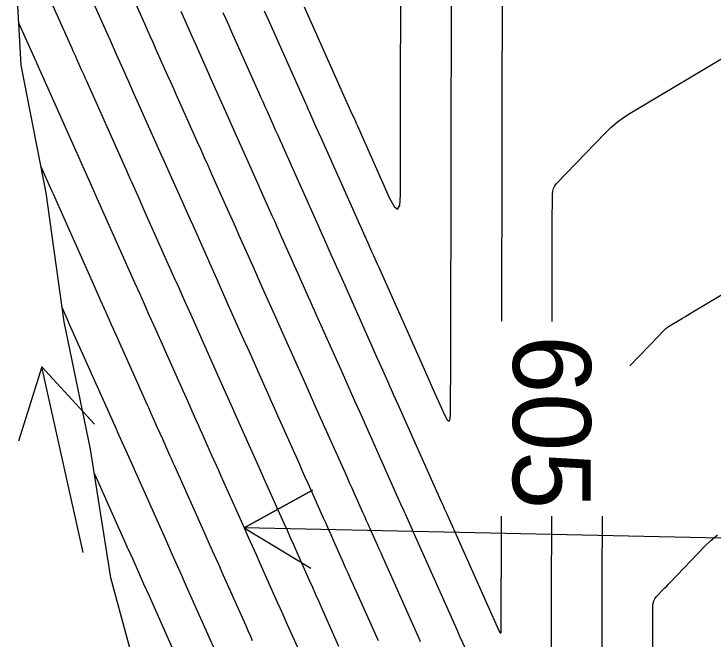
# Model space of a CAD drawing. Extents: x 954385 to 988206, y 1868364 to 1924553.
# Drawn here: x 958001.8 to 958055.6, y 1918662.3 to 1918710.4 of the extents above; entities that cross this region are included whole.
import ezdxf

# ---------------------------------------------------------------- set-up
doc = ezdxf.new("R2010")
doc.units = 0
for name, color, linetype in [('24', 7, 'Continuous'), ('26', 7, 'Continuous'), ('5', 7, 'Continuous'), ('6', 7, 'Continuous'), ('7', 7, 'Continuous')]:
    doc.layers.add(name, color=color, linetype=linetype)

msp = doc.modelspace()

# ---------------------------------------------------------------- linework, layer by layer
at = {"layer": '24'}
msp.add_lwpolyline([(958049.573, 1918532.557), (958045.001, 1918541.78), (958040.731, 1918551.071), (958036.858, 1918560.45), (958033.237, 1918569.886), (958029.666, 1918579.334), (958026.587, 1918588.891), (958024.254, 1918598.617), (958022.107, 1918608.383), (958020.314, 1918618.23), (958018.751, 1918628.128), (958016.763, 1918637.93), (958014.212, 1918647.607), (958011.88, 1918657.332), (958009.258, 1918666.992), (958007.706, 1918676.893), (958005.664, 1918686.683), (958004.274, 1918696.62), (958002.36, 1918706.439), (958001.804, 1918716.563)], dxfattribs=at)
at = {"layer": '26'}
for points in [[(958007.131, 1918668.928), (958003.951, 1918683.225), (958008.008, 1918678.804), (958003.951, 1918683.225), (958002.151, 1918677.502)], [(958107.131, 1918668.928), (958019.526, 1918670.834), (958024.786, 1918673.72), (958019.526, 1918670.834), (958024.656, 1918667.722)]]:
    msp.add_lwpolyline(points, dxfattribs=at)
at = {"layer": '6'}
for points in [[(958014.64, 1918710.621), (958014.93, 1918709.973), (958015.219, 1918709.325), (958015.509, 1918708.677), (958015.798, 1918708.029), (958017.073, 1918705.173), (958017.303, 1918704.656), (958017.534, 1918704.14), (958017.764, 1918703.623), (958017.995, 1918703.107), (958018.917, 1918701.042), (958019.147, 1918700.525), (958019.378, 1918700.009), (958019.609, 1918699.493), (958019.839, 1918698.976), (958021.671, 1918694.873), (958021.858, 1918694.455), (958022.044, 1918694.037), (958022.231, 1918693.619), (958022.417, 1918693.201), (958023.228, 1918691.386), (958023.382, 1918691.04), (958023.537, 1918690.694), (958023.691, 1918690.348), (958023.846, 1918690.002), (958024.464, 1918688.618), (958024.618, 1918688.271), (958024.773, 1918687.925), (958024.927, 1918687.579), (958025.081, 1918687.233), (958026.964, 1918683.015), (958027.33, 1918682.197), (958027.695, 1918681.378), (958028.06, 1918680.56), (958028.426, 1918679.741), (958030.835, 1918674.344), (958030.937, 1918674.116), (958031.039, 1918673.888), (958031.14, 1918673.66), (958031.242, 1918673.432), (958031.679, 1918672.454), (958031.766, 1918672.259), (958031.854, 1918672.063), (958031.941, 1918671.867), (958032.028, 1918671.672), (958032.377, 1918670.89), (958032.464, 1918670.694), (958032.552, 1918670.498), (958032.639, 1918670.303), (958032.726, 1918670.107), (958035.901, 1918662.994), (958035.957, 1918662.87), (958036.012, 1918662.747), (958036.067, 1918662.624), (958036.122, 1918662.5), (958036.563, 1918661.512)], [(958043.244, 1918686.729), (958043.26, 1918694.15), (958043.265, 1918696.527), (958043.286, 1918696.754), (958043.347, 1918696.964), (958043.449, 1918697.157), (958043.591, 1918697.335), (958047.331, 1918701.226), (958047.774, 1918701.658), (958048.243, 1918702.057), (958048.738, 1918702.424), (958049.258, 1918702.758), (958057.444, 1918707.645)], [(958020.184, 1918662.132), (958020.014, 1918662.513), (958019.844, 1918662.894), (958019.674, 1918663.276), (958017.918, 1918667.212), (958017.569, 1918667.995), (958017.219, 1918668.779), (958016.869, 1918669.562), (958016.52, 1918670.345), (958014.179, 1918675.587), (958014.067, 1918675.837), (958013.955, 1918676.088), (958013.843, 1918676.339), (958013.731, 1918676.59), (958013.255, 1918677.656), (958013.06, 1918678.094), (958012.864, 1918678.533), (958012.375, 1918679.629), (958012.179, 1918680.067), (958012.081, 1918680.286), (958009.745, 1918685.519), (958009.323, 1918686.464), (958008.901, 1918687.41), (958008.479, 1918688.355), (958008.057, 1918689.3), (958004.835, 1918696.517), (958004.722, 1918696.771), (958003.875, 1918698.668)], [(958043.175, 1918655.381), (958043.193, 1918662.483), (958043.195, 1918663.421), (958043.197, 1918664.36), (958043.199, 1918665.298), (958043.201, 1918666.236), (958043.212, 1918671.179), (958043.213, 1918671.729)]]:
    msp.add_lwpolyline(points, dxfattribs=at)
at = {"layer": '7'}
for points in [[(958002.39, 1918716.411), (958006.254, 1918707.765), (958006.346, 1918707.56), (958006.438, 1918707.354), (958006.529, 1918707.149), (958006.621, 1918706.943), (958006.988, 1918706.121), (958007.08, 1918705.915), (958007.172, 1918705.71), (958007.263, 1918705.504), (958007.355, 1918705.299), (958010.318, 1918698.664), (958010.457, 1918698.351), (958010.597, 1918698.039), (958010.736, 1918697.726), (958010.876, 1918697.414), (958011.434, 1918696.164), (958011.713, 1918695.539), (958011.992, 1918694.914), (958014.125, 1918690.134), (958014.44, 1918689.429), (958014.755, 1918688.723), (958015.07, 1918688.018), (958015.385, 1918687.312), (958016.865, 1918683.997), (958017.07, 1918683.538), (958017.275, 1918683.079), (958017.48, 1918682.62), (958017.685, 1918682.161), (958018.504, 1918680.326), (958018.709, 1918679.867), (958018.914, 1918679.408), (958019.119, 1918678.949), (958019.323, 1918678.49), (958020.32, 1918676.258), (958020.554, 1918675.733), (958020.789, 1918675.208), (958021.023, 1918674.683), (958021.257, 1918674.158), (958022.583, 1918671.189), (958022.828, 1918670.64), (958023.073, 1918670.092), (958023.317, 1918669.544), (958023.562, 1918668.996), (958024.54, 1918666.803), (958024.785, 1918666.255), (958025.029, 1918665.707), (958025.274, 1918665.159), (958025.518, 1918664.611), (958026.805, 1918661.728)], [(958006.033, 1918715.467), (958009.049, 1918708.717), (958009.207, 1918708.364), (958009.365, 1918708.011), (958009.522, 1918707.658), (958009.68, 1918707.305), (958010.31, 1918705.893), (958010.468, 1918705.54), (958010.626, 1918705.187), (958010.783, 1918704.834), (958010.941, 1918704.48), (958013.116, 1918699.61), (958013.32, 1918699.153), (958013.524, 1918698.696), (958013.728, 1918698.238), (958013.932, 1918697.781), (958014.748, 1918695.952), (958014.952, 1918695.495), (958015.157, 1918695.038), (958015.361, 1918694.581), (958015.565, 1918694.124), (958017.16, 1918690.552), (958017.421, 1918689.966), (958017.683, 1918689.38), (958017.944, 1918688.794), (958018.205, 1918688.209), (958019.258, 1918685.852), (958019.516, 1918685.273), (958019.774, 1918684.694), (958020.033, 1918684.116), (958020.291, 1918683.537), (958021.324, 1918681.222), (958021.583, 1918680.643), (958021.841, 1918680.065), (958022.099, 1918679.486), (958022.358, 1918678.907), (958023.757, 1918675.773), (958023.981, 1918675.271), (958024.205, 1918674.768), (958024.43, 1918674.266), (958024.654, 1918673.763), (958025.615, 1918671.61), (958025.808, 1918671.18), (958026, 1918670.749), (958026.192, 1918670.319), (958026.384, 1918669.888), (958027.152, 1918668.166), (958027.345, 1918667.735), (958027.537, 1918667.304), (958027.729, 1918666.874), (958027.921, 1918666.443), (958029.837, 1918662.15)], [(958009.676, 1918714.523), (958011.845, 1918709.669), (958012.068, 1918709.168), (958012.292, 1918708.668), (958012.515, 1918708.167), (958012.739, 1918707.667), (958013.633, 1918705.664), (958013.856, 1918705.164), (958014.08, 1918704.663), (958014.303, 1918704.163), (958014.527, 1918703.662), (958015.913, 1918700.556), (958016.182, 1918699.954), (958016.451, 1918699.352), (958016.72, 1918698.75), (958016.988, 1918698.149), (958018.098, 1918695.663), (958018.349, 1918695.1), (958018.6, 1918694.537), (958018.852, 1918693.975), (958019.103, 1918693.412), (958020.194, 1918690.969), (958020.402, 1918690.503), (958020.61, 1918690.037), (958020.818, 1918689.571), (958021.026, 1918689.105), (958021.857, 1918687.242), (958022.065, 1918686.776), (958022.273, 1918686.31), (958022.481, 1918685.844), (958022.689, 1918685.378), (958024.144, 1918682.119), (958024.456, 1918681.42), (958024.768, 1918680.721), (958025.08, 1918680.023), (958025.392, 1918679.324), (958027.296, 1918675.059), (958027.459, 1918674.693), (958027.622, 1918674.328), (958027.785, 1918673.963), (958027.948, 1918673.598), (958028.647, 1918672.032), (958028.787, 1918671.719), (958028.927, 1918671.406), (958029.066, 1918671.093), (958029.206, 1918670.78), (958029.765, 1918669.528), (958029.904, 1918669.214), (958030.044, 1918668.901), (958030.184, 1918668.588), (958030.324, 1918668.275), (958032.869, 1918662.572), (958032.977, 1918662.331), (958033.084, 1918662.09)], [(958021.074, 1918710.639), (958021.225, 1918710.3), (958021.376, 1918709.962), (958024.244, 1918703.536), (958024.343, 1918703.314), (958024.442, 1918703.093), (958024.541, 1918702.872), (958024.639, 1918702.65), (958025.035, 1918701.765), (958025.232, 1918701.323), (958025.43, 1918700.88), (958028.817, 1918693.293), (958029.047, 1918692.779), (958029.343, 1918692.114), (958029.486, 1918691.795), (958029.771, 1918691.156), (958029.866, 1918690.944), (958033.08, 1918683.742), (958033.315, 1918683.217), (958033.549, 1918682.692), (958033.784, 1918682.167), (958034.018, 1918681.642), (958034.956, 1918679.541), (958035.161, 1918679.153), (958035.308, 1918679.041), (958035.397, 1918679.203), (958035.427, 1918679.641), (958035.437, 1918684.053), (958035.441, 1918685.93), (958035.442, 1918686.399), (958035.443, 1918686.868), (958035.444, 1918687.337), (958035.445, 1918687.806), (958035.46, 1918694.994), (958035.473, 1918701.059), (958035.475, 1918702.34), (958035.478, 1918703.622), (958035.481, 1918704.904), (958035.483, 1918706.185), (958035.496, 1918712.107)], [(958039.396, 1918712.046), (958039.378, 1918703.055), (958039.366, 1918697.605), (958039.348, 1918688.682), (958039.347, 1918688.213), (958039.346, 1918687.744), (958039.345, 1918687.275), (958039.344, 1918686.806), (958039.344, 1918686.737)], [(958024.16, 1918710.939), (958027.83, 1918702.717), (958027.962, 1918702.422), (958028.159, 1918701.98), (958028.225, 1918701.832), (958030.707, 1918696.272), (958031.079, 1918695.57), (958031.346, 1918695.366), (958031.506, 1918695.66), (958031.561, 1918696.453), (958031.57, 1918700.652), (958031.573, 1918701.699), (958031.575, 1918702.746), (958031.577, 1918703.793), (958031.579, 1918704.84), (958031.593, 1918711.378)], [(958039.312, 1918671.737), (958039.312, 1918671.677), (958039.311, 1918671.333), (958039.31, 1918670.99), (958039.31, 1918670.646), (958039.309, 1918670.303), (958039.294, 1918663.701), (958039.294, 1918663.592), (958039.294, 1918663.484), (958039.294, 1918663.375), (958039.293, 1918663.266), (958039.292, 1918662.817), (958039.287, 1918662.739), (958039.271, 1918662.711), (958039.245, 1918662.731), (958039.209, 1918662.799), (958038.936, 1918663.41), (958038.933, 1918663.416), (958035.129, 1918671.939), (958035.059, 1918672.096), (958034.989, 1918672.252), (958034.85, 1918672.564), (958034.781, 1918672.72), (958034.711, 1918672.876), (958034.496, 1918673.357), (958034.374, 1918673.63), (958031.46, 1918680.158), (958031.041, 1918681.097), (958030.622, 1918682.035), (958030.203, 1918682.973), (958029.784, 1918683.911), (958027.474, 1918689.088), (958027.272, 1918689.541), (958027.07, 1918689.993), (958026.666, 1918690.898), (958026.464, 1918691.351), (958026.262, 1918691.803), (958025.732, 1918692.99), (958025.488, 1918693.536), (958025.244, 1918694.083), (958022.634, 1918699.928), (958022.47, 1918700.297), (958022.305, 1918700.666), (958022.14, 1918701.035), (958021.976, 1918701.404), (958021.317, 1918702.879), (958021.152, 1918703.248), (958020.988, 1918703.616), (958020.823, 1918703.985), (958020.659, 1918704.354), (958018.591, 1918708.985), (958018.369, 1918709.483), (958018.146, 1918709.982), (958017.924, 1918710.48)], [(958002.183, 1918709.668), (958003.459, 1918706.813), (958003.51, 1918706.697), (958003.562, 1918706.581), (958003.717, 1918706.233), (958003.769, 1918706.117), (958007.52, 1918697.718), (958007.669, 1918697.382), (958007.819, 1918697.046), (958008.194, 1918696.207), (958008.419, 1918695.704), (958011.091, 1918689.717), (958011.46, 1918688.892), (958011.828, 1918688.066), (958012.197, 1918687.241), (958012.565, 1918686.416), (958014.473, 1918682.141), (958014.625, 1918681.802), (958014.776, 1918681.463), (958014.927, 1918681.124), (958015.079, 1918680.785), (958015.684, 1918679.429), (958015.835, 1918679.09), (958015.987, 1918678.751), (958016.138, 1918678.412), (958016.289, 1918678.073), (958017.026, 1918676.424), (958017.199, 1918676.036), (958017.372, 1918675.648), (958017.545, 1918675.26), (958017.718, 1918674.873), (958019.552, 1918670.767), (958019.849, 1918670.101), (958020.146, 1918669.435), (958020.443, 1918668.77), (958020.74, 1918668.104), (958022.077, 1918665.108), (958022.299, 1918664.609), (958022.522, 1918664.11), (958022.744, 1918663.611), (958022.967, 1918663.112), (958023.858, 1918661.117)], [(958049.237, 1918683.307), (958051.463, 1918685.623), (958051.702, 1918685.871), (958051.94, 1918686.119), (958052.001, 1918686.179), (958052.066, 1918686.234), (958052.135, 1918686.285), (958052.207, 1918686.332), (958053.271, 1918686.967), (958053.473, 1918687.088), (958053.675, 1918687.209), (958053.877, 1918687.329), (958054.079, 1918687.45), (958060.723, 1918691.422)], [(958017.271, 1918661.443), (958015.096, 1918666.32), (958014.694, 1918667.221), (958014.292, 1918668.122), (958013.89, 1918669.022), (958013.488, 1918669.923), (958010.64, 1918676.301), (958010.538, 1918676.528), (958010.437, 1918676.756), (958010.133, 1918677.437), (958009.778, 1918678.232), (958009.689, 1918678.431), (958006.091, 1918686.492), (958005.916, 1918686.883), (958005.508, 1918687.796)], [(958008.004, 1918674.993), (958010.525, 1918669.347), (958010.945, 1918668.406), (958011.365, 1918667.465), (958011.785, 1918666.524), (958012.205, 1918665.583), (958014.869, 1918659.611)], [(958047.078, 1918656.257), (958047.096, 1918663.642), (958047.098, 1918664.439), (958047.1, 1918665.236), (958047.102, 1918666.032), (958047.104, 1918666.829), (958047.114, 1918671.721)], [(958050.982, 1918657.474), (958051, 1918664.857), (958051.017, 1918665.042), (958051.067, 1918665.215), (958051.151, 1918665.374), (958051.268, 1918665.519), (958051.802, 1918666.073), (958051.935, 1918666.212), (958052.069, 1918666.351), (958052.202, 1918666.489), (958052.335, 1918666.628), (958054.981, 1918669.381), (958055.469, 1918669.855), (958055.984, 1918670.294)]]:
    msp.add_lwpolyline(points, dxfattribs=at)

# ---------------------------------------------------------------- texts
at = {"layer": '5'}
msp.add_text('605', height=6, rotation=269.8802, dxfattribs=at).set_placement((958040.242, 1918685.664))

doc.saveas('drawing.dxf')
